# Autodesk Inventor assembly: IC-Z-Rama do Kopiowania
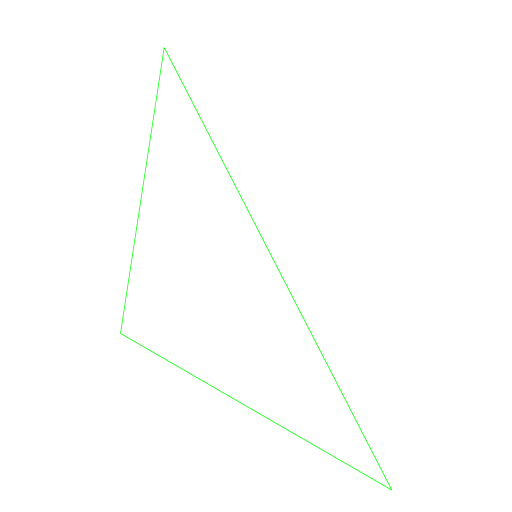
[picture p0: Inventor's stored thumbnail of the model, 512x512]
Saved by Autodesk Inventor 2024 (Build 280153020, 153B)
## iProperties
_SolveAssemblyDoc: Frame Generator Solve Assembly
_Version: 25.0.0
Company: ATC
Created: 2023-03
Part Number: IC-Z-Rama do Kopiowania
Document SubType Name: Assembly
Designer: Andrzej Jaskulski
Checked By: A.J.
Engr Approved By: Andrzej Jaskulski
Mfg Approved By: Andrzej Jaskulski
Authority: A.J.
Author: Andrzej Jaskulski
Revision Number: 1/24
Title: A.J.: Kurs R2024-MEP
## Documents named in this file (3)
- C:\Users\AndJas\Documents\R2024-MEP\Obszar roboczy\IC-Z-Rama do Kopiowania.iam
- C:\Users\AndJas\Documents\R2024-MEP\Obszar roboczy\IC-CZ-Definicja Ramy.ipt
- C:\Users\AndJas\Documents\R2024-MEP\Obszar roboczy\IC-Z-Rama do Kopiowania\Frame\RAMA.iam
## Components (2 placed, 2 different names)
1. IC-CZ-Definicja Ramy:1
2. RAMA:1 [sub-assembly]
